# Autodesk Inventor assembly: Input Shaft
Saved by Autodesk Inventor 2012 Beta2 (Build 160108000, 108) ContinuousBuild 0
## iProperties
Created: 2011-01
Part Number: Input Shaft
Document SubType Name: Assembly
Designer: Beta-8540w
ClientObjectVersion: 1
Author: Beta-8540w
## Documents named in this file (2)
- C:\Inventor 2012 Essentials\Assemblies\Chapter 8\Design Accelerators\Shaft c8-06.iam
- C:\Inventor 2012 Essentials\Assemblies\Chapter 8\Design Accelerators\Shaft c8-04.ipt
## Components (1 placed, 1 different names)
1. Input Shaft:1
